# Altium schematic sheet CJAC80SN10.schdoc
size 127 x 101 mm
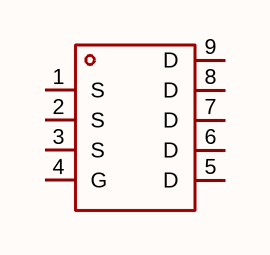
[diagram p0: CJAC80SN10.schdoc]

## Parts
Q?  cjac80sn10  [PDFN-8_L5.8-W5.0-P1.27-LS6.0-BL]  (value not drawn)

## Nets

Not connected (* = marked no-connect by the designer): Q? 1(S) 2(S) 3(S) 4(G) 5(D) 6(D) 7(D) 8(D) 9(D)

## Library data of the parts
Q? = cjac80sn10: 数量:1个N沟道;漏源电压(Vdss):100V;连续漏极电流(Id):80A;导通电阻(RDS(on)):10.5mΩ@4.5V;耗散功率(Pd):100W;阈值电压(Vgs(th)):2.5V;; Manufacturer: CJ(江苏长电/长晶); AddInBom: yes; ModelId: 64dd0a0ad16f4146a485008a6fd3b168; ModelTransform: 193.7004,238.189,0,0,0,0,0,0,0; Number: 1个N沟道; Drain to Source Voltage: 100V; Current - Continuous Drain(Id): 80A; Pd - Power Dissipation: 100W; Gate Threshold Voltage (Vgs(th)): 2.5V; Gate Charge(Qg): 100nC@10V; Input Capacitance(Ciss): 3.15nF; Reverse Transfer Capacitance (Crss@Vds): 8pF; Type: N沟道; Output Capacitance(Coss): 650pF; Vgs: ±20V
